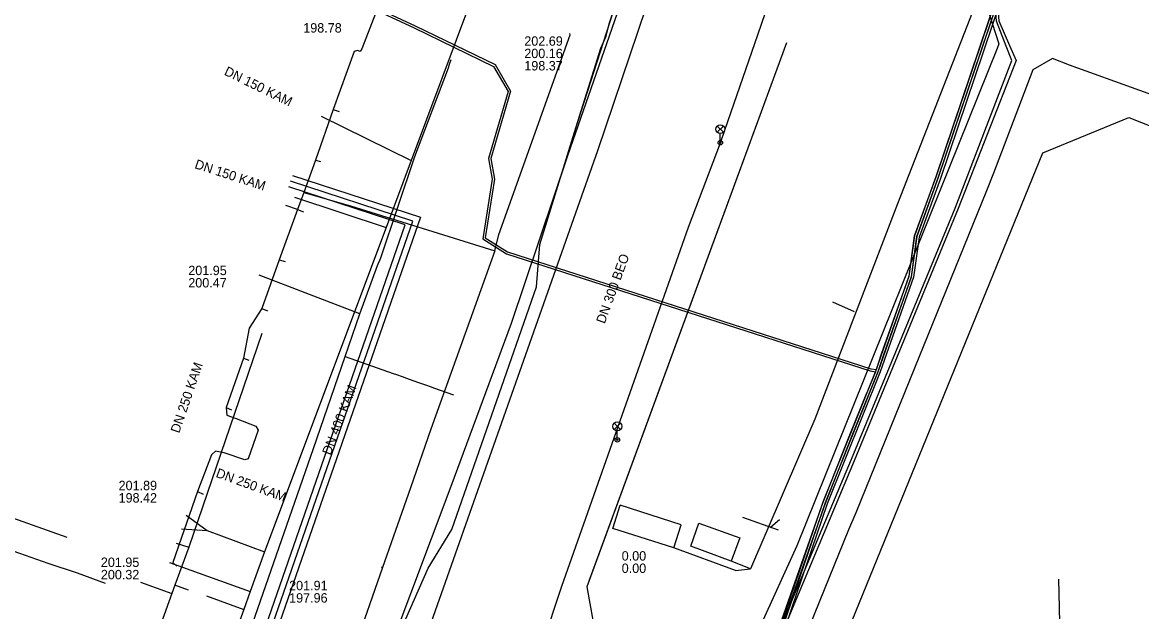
# Model space of a CAD drawing. Extents: x -598932 to -598196, y -1162210 to -1161504.
# Drawn here: x -598647.1 to -598551.8, y -1162136.5 to -1162086.4 of the extents above; entities that cross this region are included whole.
import ezdxf

# ---------------------------------------------------------------- set-up
doc = ezdxf.new("R2010")
doc.units = 0
for name, color, linetype in [('Vrstva 1', 7, 'Continuous'), ('Vrstva 12', 7, 'Continuous'), ('Vrstva 14', 7, 'Continuous'), ('Vrstva 25', 7, 'Continuous'), ('Vrstva 26', 7, 'Continuous'), ('Vrstva 33', 7, 'Continuous'), ('Vrstva 4', 7, 'Continuous'), ('Vrstva 42', 7, 'Continuous'), ('Vrstva 44', 7, 'Continuous'), ('Vrstva 55', 7, 'Continuous'), ('Vrstva 58', 7, 'Continuous'), ('Vrstva 9', 7, 'Continuous')]:
    doc.layers.add(name, color=color, linetype=linetype)

msp = doc.modelspace()

# ---------------------------------------------------------------- linework, layer by layer
at = {"layer": 'Vrstva 1'}
for p, q in [((-598582.03, -1162088.17), (-598599.03, -1162134.42)), ((-598582.029, -1162088.174), (-598598.845, -1162133.922)), ((-598576.25, -1162111.04), (-598578.1, -1162110.21)), ((-598582.72, -1162129.6), (-598585.75, -1162128.53)), ((-598582.64, -1162128.72), (-598583.39, -1162129.38)), ((-598599.03, -1162134.42), (-598594.47, -1162159.01)), ((-598599.027, -1162134.423), (-598594.47, -1162159.01))]:
    msp.add_line(p, q, dxfattribs=at)
at = {"layer": 'Vrstva 12'}
for p, q in [((-598563.96, -1162088.26), (-598564.12, -1162088.67)), ((-598558.659, -1162143.26), (-598558.872, -1162133.76))]:
    msp.add_line(p, q, dxfattribs=at)
for points in [[(-598553.63, -1162059.2), (-598553.03, -1162059.41), (-598552.81, -1162059.79), (-598553.17, -1162060.16), (-598554.06, -1162060.58), (-598555.74, -1162062.92), (-598559.51, -1162066.12), (-598564.16, -1162079.63), (-598564.97, -1162082.87), (-598565.09, -1162084.75), (-598563.96, -1162088.26)], [(-598564.12, -1162088.67), (-598581.15, -1162130.92), (-598584.34, -1162137.89), (-598586.52, -1162142.25), (-598586.97, -1162144.37), (-598588.32, -1162146.42)]]:
    msp.add_lwpolyline(points, dxfattribs=at)
at = {"layer": 'Vrstva 14'}
for p, q in [((-598618.34, -1162111.2), (-598626.9, -1162107.93)), ((-598619.58, -1162114.82), (-598615.5, -1162116.27)), ((-598611.997, -1162117.511), (-598610.371, -1162118.102))]:
    msp.add_line(p, q, dxfattribs=at)
for points in [[(-598644.33, -1162184.57), (-598644.18, -1162184.13), (-598638.95, -1162170.52), (-598635.41, -1162160.34), (-598631.28, -1162148.51), (-598627.24, -1162136.89), (-598622.28, -1162122.66), (-598619.58, -1162114.82), (-598618.34, -1162111.2), (-598616.83, -1162107.09), (-598616.56, -1162106.45), (-598613.65, -1162097.83), (-598610.8, -1162090.29), (-598610.7, -1162090), (-598610.57, -1162089.6)], [(-598520.2, -1162103.687), (-598520.797, -1162103.701), (-598523.92, -1162102.55), (-598529.36, -1162100.54), (-598540.727, -1162096.282), (-598551.979, -1162092.226), (-598557.96, -1162090.07), (-598559.41, -1162089.52), (-598561.075, -1162090.464), (-598563.736, -1162097.476), (-598564.409, -1162099.249)], [(-598564.409, -1162099.249), (-598565.028, -1162100.748), (-598571.148, -1162115.82), (-598576.14, -1162128.127), (-598576.752, -1162129.574), (-598582.543, -1162143.824), (-598585.362, -1162150.375), (-598588.164, -1162154.078), (-598591.021, -1162160.688)], [(-598615.5, -1162116.27), (-598615.221, -1162116.368), (-598614.749, -1162116.535), (-598614.372, -1162116.669), (-598614.137, -1162116.753), (-598613.335, -1162117.036), (-598612.676, -1162117.27), (-598612.346, -1162117.387), (-598611.997, -1162117.511)]]:
    msp.add_lwpolyline(points, dxfattribs=at)
at = {"layer": 'Vrstva 25'}
msp.add_lwpolyline([(-598635.714, -1162166.241), (-598634.381, -1162162.409), (-598634.38, -1162162.406), (-598613.829, -1162103.32), (-598624.234, -1162099.93)], dxfattribs=at)
at = {"layer": 'Vrstva 26'}
for points in [[(-598624.079, -1162099.455), (-598613.189, -1162103.003), (-598633.909, -1162162.573), (-598635.071, -1162165.915)], [(-598636.07, -1162165.741), (-598634.853, -1162162.244), (-598614.469, -1162103.637), (-598624.389, -1162100.405)]]:
    msp.add_lwpolyline(points, dxfattribs=at)
at = {"layer": 'Vrstva 33'}
for p, q in [((-598587.93, -1162095.247), (-598587.4, -1162095.777)), ((-598587.93, -1162095.777), (-598587.4, -1162095.247)), ((-598587.665, -1162096.662), (-598587.665, -1162095.887)), ((-598596.695, -1162120.505), (-598596.165, -1162121.035)), ((-598596.695, -1162121.035), (-598596.165, -1162120.505)), ((-598596.43, -1162121.92), (-598596.43, -1162121.145))]:
    msp.add_line(p, q, dxfattribs=at)
for centre, radius in [((-598587.665, -1162095.512), 0.375), ((-598587.665, -1162096.662), 0.19), ((-598587.665, -1162096.662), 0.05), ((-598596.43, -1162120.77), 0.375), ((-598596.43, -1162121.92), 0.19), ((-598596.43, -1162121.92), 0.05)]:
    msp.add_circle(centre, radius, dxfattribs=at)
at = {"layer": 'Vrstva 42'}
for p, q in [((-598564.52, -1162081.19), (-598572.6, -1162101.87)), ((-598572.6, -1162101.87), (-598579.61, -1162120.17)), ((-598579.61, -1162120.17), (-598585.093, -1162132.876)), ((-598596.8, -1162129.44), (-598596.18, -1162127.47)), ((-598591.01, -1162129.13), (-598596.18, -1162127.47)), ((-598591.63, -1162131.1), (-598596.8, -1162129.44)), ((-598591.63, -1162131.1), (-598591.01, -1162129.13)), ((-598590.18, -1162130.94), (-598589.5, -1162129)), ((-598589.5, -1162129), (-598586, -1162130.24)), ((-598586, -1162130.24), (-598586.75, -1162132.23)), ((-598586.367, -1162133.021), (-598591.63, -1162131.1)), ((-598586.75, -1162132.23), (-598590.18, -1162130.94)), ((-598585.093, -1162132.876), (-598586.75, -1162132.23)), ((-598586.367, -1162133.021), (-598585.093, -1162132.876))]:
    msp.add_line(p, q, dxfattribs=at)
for points in [[(-598587.25, -1162051.43), (-598590.34, -1162055.11), (-598589.81, -1162057.67), (-598592.26, -1162064.33), (-598592.83, -1162066.93), (-598592.96, -1162069.47), (-598592.36, -1162074.22), (-598595.78, -1162083.76), (-598600.67, -1162097.79), (-598605.47, -1162112.02), (-598610.59, -1162125.88), (-598615.71, -1162139.45), (-598620.8, -1162152.27), (-598625.98, -1162166.85), (-598630.7, -1162180.39), (-598633.77, -1162187.31)], [(-598637.628, -1162206.96), (-598636.43, -1162204.24), (-598635.74, -1162203.22), (-598635.28, -1162201.48), (-598636.8, -1162192.31), (-598635.05, -1162189.92), (-598634.93, -1162189.45), (-598633.61, -1162187.8), (-598631.25, -1162182.14), (-598627.64, -1162172.38), (-598622.09, -1162156.7), (-598617.33, -1162144.38), (-598616, -1162140.73), (-598612.52, -1162132.81), (-598610.5, -1162129.53), (-598603.32, -1162108.9), (-598603.03, -1162105.32), (-598600.08, -1162095.77), (-598597.82, -1162088.64), (-598597.39, -1162087.61), (-598597.12, -1162086.56), (-598595.92, -1162082.91)], [(-598637.628, -1162206.96), (-598636.43, -1162204.24), (-598635.74, -1162203.22), (-598635.28, -1162201.48), (-598636.8, -1162192.31), (-598635.05, -1162189.92), (-598634.93, -1162189.45), (-598633.61, -1162187.8), (-598631.25, -1162182.14), (-598627.64, -1162172.38), (-598622.09, -1162156.7), (-598617.33, -1162144.38), (-598616, -1162140.73), (-598612.52, -1162132.81), (-598610.5, -1162129.53), (-598603.32, -1162108.9), (-598603.03, -1162105.32), (-598600.08, -1162095.77), (-598595.92, -1162082.91)], [(-598597.82, -1162088.64), (-598597.39, -1162087.61), (-598597.12, -1162086.56)]]:
    msp.add_lwpolyline(points, dxfattribs=at)
at = {"layer": 'Vrstva 44'}
for points in [[(-598563.332, -1162088.466), (-598564.168, -1162086.347), (-598564.248, -1162085.266), (-598564.27, -1162084.971), (-598561.75, -1162078.194), (-598558.739, -1162070.098), (-598554.966, -1162066.097), (-598554.143, -1162064.182)], [(-598553.94, -1162064.291), (-598554.78, -1162066.24), (-598558.57, -1162070.23), (-598564.07, -1162085.01), (-598563.98, -1162086.31), (-598563.067, -1162088.389)], [(-598619.153, -1162084.363), (-598613.716, -1162086.904), (-598606.953, -1162090.175), (-598605.727, -1162092.3), (-598607.4, -1162097.997), (-598607.089, -1162099.763), (-598607.885, -1162104.838), (-598605.856, -1162106.119), (-598574.908, -1162116.065), (-598574.461, -1162116.139), (-598575.191, -1162117.929)], [(-598619.069, -1162084.181), (-598613.63, -1162086.724), (-598606.811, -1162090.021), (-598605.511, -1162092.274), (-598607.194, -1162098.009), (-598606.887, -1162099.761), (-598607.667, -1162104.74), (-598605.77, -1162105.937), (-598574.86, -1162115.871), (-598574.389, -1162115.947), (-598573.945, -1162114.598)], [(-598573.945, -1162114.598), (-598571.598, -1162108.016), (-598571.138, -1162104.576), (-598569.304, -1162099.577), (-598564.154, -1162084.367)], [(-598582.091, -1162136.821), (-598578.726, -1162127.295), (-598576.455, -1162121.556), (-598574.226, -1162116.095), (-598573.755, -1162114.662), (-598571.402, -1162108.064), (-598570.942, -1162104.624), (-598569.116, -1162099.643), (-598564.248, -1162085.266)], [(-598588.08, -1162147.33), (-598587.597, -1162146.385), (-598583.448, -1162140.039), (-598583.007, -1162138.994), (-598582.091, -1162136.821), (-598576.501, -1162123.564), (-598567.689, -1162102.217), (-598562.853, -1162089.678), (-598563.332, -1162088.466)], [(-598563.067, -1162088.389), (-598562.504, -1162089.671), (-598567.429, -1162102.258), (-598576.271, -1162123.709), (-598582.804, -1162139.257), (-598582.996, -1162139.715), (-598583.188, -1162140.172), (-598587.178, -1162146.613), (-598587.83, -1162147.52)], [(-598611.455, -1162206.96), (-598610.004, -1162202.273), (-598609.085, -1162201.739), (-598608.659, -1162201.492), (-598603.83, -1162198.686), (-598601.685, -1162197.44), (-598600.293, -1162196.631), (-598600.255, -1162196.59), (-598599.887, -1162196.194), (-598599.417, -1162195.688), (-598600.131, -1162191.613), (-598599.648, -1162187.647), (-598593.054, -1162168.447), (-598587.309, -1162152.141), (-598583.791, -1162147.614), (-598582.92, -1162144.527), (-598582.996, -1162139.715), (-598583.007, -1162138.994), (-598583.01, -1162138.824), (-598578.914, -1162127.225), (-598576.641, -1162121.482), (-598575.191, -1162117.929)]]:
    msp.add_lwpolyline(points, dxfattribs=at)
at = {"layer": 'Vrstva 55'}
for p, q in [((-598620.6, -1162093.84), (-598622.11, -1162098.16)), ((-598620.6, -1162093.84), (-598620.09, -1162094.01)), ((-598622.11, -1162098.16), (-598623.1, -1162100.89)), ((-598622.11, -1162098.16), (-598621.69, -1162098.27)), ((-598623.1, -1162100.89), (-598623.64, -1162102.35)), ((-598623.64, -1162102.35), (-598625.2, -1162106.62)), ((-598623.64, -1162102.35), (-598624.63, -1162102)), ((-598623.64, -1162102.35), (-598623.13, -1162102.53)), ((-598606.86, -1162105.84), (-598606.5, -1162104.46)), ((-598625.2, -1162106.62), (-598626.68, -1162110.76)), ((-598625.2, -1162106.62), (-598624.68, -1162106.75)), ((-598626.68, -1162110.76), (-598626.2, -1162110.94)), ((-598628.24, -1162114.97), (-598629.72, -1162119.16)), ((-598628.24, -1162114.97), (-598627.77, -1162115.15)), ((-598629.72, -1162119.16), (-598629.26, -1162119.37)), ((-598632.14, -1162126.32), (-598631.66, -1162126.54)), ((-598616.41, -1162132.77), (-598616.5, -1162132.75)), ((-598611.18, -1162164.448), (-598601.774, -1162136.233))]:
    msp.add_line(p, q, dxfattribs=at)
for points in [[(-598635.847, -1162206.96), (-598629.97, -1162189.7), (-598621.09, -1162162.42), (-598598.1, -1162097.33), (-598589.15, -1162070.89), (-598592.61, -1162069.46), (-598587.52, -1162054.61), (-598584.27, -1162048.71), (-598581.62, -1162049.12), (-598567.59, -1162009.46), (-598573.28, -1162007.22), (-598571.851, -1162001.315), (-598576.64, -1161997.21), (-598590.4, -1161991.37), (-598599.45, -1161987.03), (-598615.67, -1161976.28), (-598632.44, -1161961.96), (-598678.26, -1161917.47), (-598684.987, -1161911.745), (-598688.029, -1161910.224), (-598691.806, -1161909.122), (-598694.533, -1161909.122), (-598697.86, -1161910.3), (-598707.4, -1161922.62)], [(-598587.64, -1162096.67), (-598587.271, -1162095.598), (-598584.453, -1162087.419), (-598577.94, -1162068.51), (-598575.783, -1162062.349), (-598571.189, -1162049.225), (-598569.71, -1162045), (-598563.847, -1162028.227), (-598561.51, -1162021.54)], [(-598613.35, -1162077.93), (-598613.5, -1162078.21), (-598614.65, -1162079.88), (-598615.58, -1162081.35), (-598615.52, -1162081.52), (-598615.75, -1162081.62), (-598615.54, -1162082.2), (-598614.77, -1162082.45), (-598614.61, -1162082.89), (-598615.18, -1162084.59), (-598615.63, -1162084.84), (-598616.42, -1162084.62), (-598616.66, -1162084.8), (-598618.18, -1162088.68), (-598618.32, -1162088.91), (-598618.53, -1162088.83), (-598618.83, -1162088.91), (-598620.6, -1162093.84)], [(-598606.5, -1162104.46), (-598600.43, -1162087.5), (-598600.47, -1162087.38)], [(-598601.774, -1162136.233), (-598601.15, -1162134.35), (-598590.37, -1162103.84), (-598587.64, -1162096.67)], [(-598623.1, -1162100.89), (-598619.12, -1162102.04), (-598606.86, -1162105.84)], [(-598606.86, -1162105.84), (-598612.3, -1162121.01), (-598614.04, -1162126), (-598616.41, -1162132.77)], [(-598626.68, -1162110.76), (-598627.75, -1162112.43), (-598628.24, -1162114.97)], [(-598682.95, -1162115.03), (-598682.67, -1162114.1), (-598672.98, -1162117.54), (-598663.35, -1162120.95), (-598663.94, -1162122.89), (-598653.33, -1162126.63), (-598643.27, -1162130.18)], [(-598629.72, -1162119.16), (-598629.65, -1162119.81), (-598628.87, -1162120.11), (-598627.2, -1162120.76), (-598627, -1162121.1), (-598627.83, -1162123.52), (-598628.13, -1162123.62), (-598629.89, -1162123.02), (-598630.61, -1162122.87), (-598630.95, -1162123.19), (-598632.14, -1162126.32)], [(-598632.14, -1162126.32), (-598634.26, -1162132.35), (-598633.91, -1162132.66)], [(-598652.14, -1162129.89), (-598649.68, -1162130.73), (-598647.29, -1162131.54), (-598644.88, -1162132.4), (-598642.4, -1162133.23), (-598640.01, -1162134.1)], [(-598616.41, -1162132.77), (-598618.82, -1162139.67), (-598621.46, -1162147.07)]]:
    msp.add_lwpolyline(points, dxfattribs=at)
at = {"layer": 'Vrstva 58'}
for points in [[(-598564.189, -1162084.364), (-598569.319, -1162099.564), (-598571.135, -1162104.591), (-598571.625, -1162108.002), (-598574.427, -1162116.01), (-598578.938, -1162127.21), (-598582.91, -1162138.837), (-598582.91, -1162144.521), (-598583.831, -1162147.597), (-598587.348, -1162152.123), (-598593.059, -1162168.444), (-598599.696, -1162187.635), (-598600.152, -1162191.608), (-598599.367, -1162195.672), (-598600.322, -1162196.61), (-598610.009, -1162202.277), (-598611.422, -1162206.96)], [(-598564.189, -1162084.364), (-598569.319, -1162099.564), (-598571.135, -1162104.591), (-598571.625, -1162108.002), (-598574.427, -1162116.01), (-598578.938, -1162127.21), (-598582.91, -1162138.837), (-598582.91, -1162144.521), (-598583.831, -1162147.597), (-598587.348, -1162152.123), (-598593.059, -1162168.444), (-598599.696, -1162187.635), (-598600.152, -1162191.608), (-598599.367, -1162195.672), (-598600.322, -1162196.61), (-598610.009, -1162202.277), (-598611.422, -1162206.96)], [(-598564, -1162084.43), (-598569.13, -1162099.63), (-598570.94, -1162104.64), (-598571.43, -1162108.05), (-598574.24, -1162116.08), (-598578.75, -1162127.28), (-598582.71, -1162138.87), (-598582.71, -1162144.55), (-598583.65, -1162147.69), (-598587.17, -1162152.22), (-598592.87, -1162168.51), (-598599.5, -1162187.68), (-598599.95, -1162191.6), (-598599.15, -1162195.74), (-598600.2, -1162196.77), (-598609.84, -1162202.41), (-598611.213, -1162206.96)], [(-598564, -1162084.43), (-598569.13, -1162099.63), (-598570.94, -1162104.64), (-598571.43, -1162108.05), (-598574.24, -1162116.08), (-598578.75, -1162127.28), (-598582.71, -1162138.87), (-598582.71, -1162144.55), (-598583.65, -1162147.69), (-598587.17, -1162152.22), (-598592.87, -1162168.51), (-598599.5, -1162187.68), (-598599.95, -1162191.6), (-598599.15, -1162195.74), (-598600.2, -1162196.77), (-598609.84, -1162202.41), (-598611.213, -1162206.96)], [(-598563.811, -1162084.496), (-598568.941, -1162099.696), (-598570.745, -1162104.689), (-598571.235, -1162108.098), (-598574.053, -1162116.15), (-598578.562, -1162127.35), (-598582.51, -1162138.903), (-598582.51, -1162144.579), (-598583.469, -1162147.783), (-598586.992, -1162152.317), (-598592.681, -1162168.576), (-598599.304, -1162187.725), (-598599.748, -1162191.592), (-598598.933, -1162195.808), (-598600.078, -1162196.93), (-598609.671, -1162202.543), (-598611.004, -1162206.96)]]:
    msp.add_lwpolyline(points, dxfattribs=at)
at = {"layer": 'Vrstva 9'}
for p, q in [((-598621.63, -1162094.4), (-598613.98, -1162098.178)), ((-598560.23, -1162097.53), (-598552.9, -1162094.52)), ((-598552.9, -1162094.52), (-598524.27, -1162105.85)), ((-598581.57, -1162149.82), (-598560.23, -1162097.53)), ((-598623.9, -1162101.28), (-598616.11, -1162103.862)), ((-598626.68, -1162112.88), (-598632.9, -1162131.05)), ((-598633.113, -1162128.307), (-598631.32, -1162129.61)), ((-598633.525, -1162129.474), (-598631.32, -1162129.61)), ((-598631.32, -1162129.61), (-598626.44, -1162131.43)), ((-598633.954, -1162130.689), (-598632.9, -1162131.05)), ((-598634.534, -1162132.331), (-598627.664, -1162134.815)), ((-598636.991, -1162134), (-598634.321, -1162134.967)), ((-598632.923, -1162134.687), (-598634.069, -1162134.272)), ((-598631.376, -1162135.162), (-598628.215, -1162136.338))]:
    msp.add_line(p, q, dxfattribs=at)
for points in [[(-598608.83, -1162084.43), (-598613.98, -1162098.178), (-598616.11, -1162103.862), (-598626.44, -1162131.43)], [(-598632.9, -1162131.05), (-598634.069, -1162134.272), (-598634.321, -1162134.967), (-598636.149, -1162140.006), (-598637.506, -1162143.747), (-598639.477, -1162149.181), (-598644.42, -1162162.81)], [(-598626.44, -1162131.43), (-598627.664, -1162134.815), (-598628.215, -1162136.338), (-598633.76, -1162151.67)]]:
    msp.add_lwpolyline(points, dxfattribs=at)

# ---------------------------------------------------------------- texts
at = {"layer": 'Vrstva 12'}
for s, p in [('198.78', (-598623.152, -1162087.302)), ('202.69', (-598604.344, -1162088.422)), ('200.16', (-598604.344, -1162089.472)), ('198.37', (-598604.344, -1162090.522)), ('201.95', (-598632.935, -1162107.916)), ('200.47', (-598632.935, -1162108.966)), ('201.89', (-598638.865, -1162126.197)), ('198.42', (-598638.865, -1162127.247)), ('201.95', (-598640.373, -1162132.72)), ('200.32', (-598640.373, -1162133.77)), ('201.91', (-598624.355, -1162134.699)), ('197.96', (-598624.355, -1162135.749))]:
    msp.add_text(s, height=0.8, dxfattribs=at).set_placement(p)
for s, rotation, p in [('DN 150 KAM', 334, (-598629.945, -1162090.862)), ('DN 150 KAM', 342, (-598632.45, -1162098.816)), ('DN 250 KAM', 71, (-598633.713, -1162121.402)), ('DN 400 KAM', 69, (-598620.828, -1162123.271)), ('DN 250 KAM', 340, (-598630.646, -1162125.052))]:
    msp.add_text(s, height=0.8, rotation=rotation, dxfattribs=at).set_placement(p)
at = {"layer": 'Vrstva 4'}
msp.add_text('DN 300 BEO', height=0.8, rotation=70, dxfattribs=at).set_placement((-598597.506, -1162112.101))
for p in [(-598596.057, -1162132.179), (-598596.057, -1162133.229)]:
    msp.add_text('0.00', height=0.8, dxfattribs=at).set_placement(p)

doc.saveas('drawing.dxf')
